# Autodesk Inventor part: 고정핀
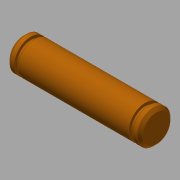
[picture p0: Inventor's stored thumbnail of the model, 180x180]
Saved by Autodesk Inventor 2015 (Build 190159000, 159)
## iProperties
Created: 2015-12
Part Number: 고정핀
Material: 스테인리스강
Document SubType Name: Modeling
Designer: mduedu
Density: 8.08 g/cm^3
Appearance: 주황색
Author: mduedu
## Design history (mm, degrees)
sketch "스케치1"
  geometry: C1 r 3 at (0, 0); 1 further point
  constraints: 1 centre point, 1 coincident
  dimensions: "d0" = 6 diameter of C1
extrude "돌출1" new body sketch "스케치1" stored distance "d1" = 24; taper "d2" = 0 deg
chamfer "모따기1" distance "d3" = 0.5; stored, may be unused: second distance "d4" = 2, angle "d5" = 45 deg
sketch "스케치2"
  geometry: L1 (-12, 2.5)-(-11.5, 3) reference; L2 (-11.5, 3)-(11.5, 3) reference; L3 (11.5, 3)-(12, 2.5) reference; L4 (12, 2.5)-(12, -2.5) reference; L5 (12, -2.5)-(11.5, -3) reference; L6 (11.5, -3)-(-11.5, -3) reference; L7 (-11.5, -3)-(-12, -2.5) reference; L8 (-12, -2.5)-(-12, 2.5) reference; L9 (10, 3)-(10.7, 3); L10 (10.7, 3)-(10.7, 2.5); L11 (10.7, 2.5)-(10, 2.5); L12 (10, 2.5)-(10, 3); L13 (0, 0)-(12, 0)
  constraints: 10 end point, 2 parallel, 1 collinear, 1 horizontal, 1 midpoint, 1 perpendicular
  dimensions: "d6" = 10 distance from line of L12 L13.start; "d7" = 5 diameter of L11 L13; "d8" = 0.7 distance of L9.start L9.end
revolve "회전1" sketch "스케치2" stored, may be unused: angle "d9" = 90 deg
node "솔리드1"
mirror "대칭1"
node "절단 모서리 투영1"
